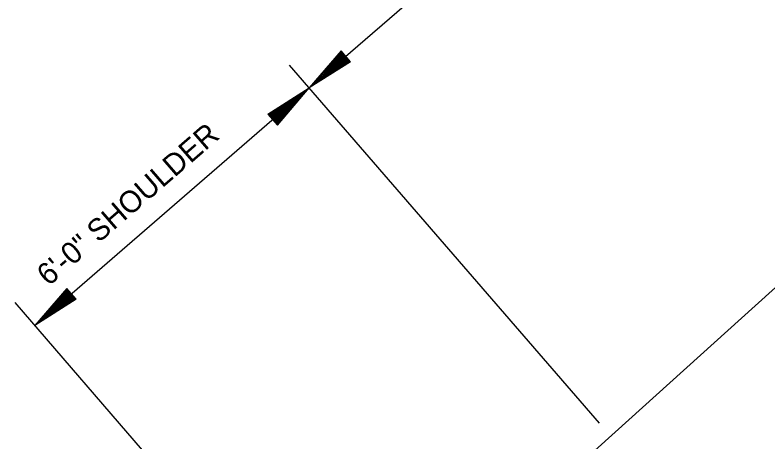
# Model space of a CAD drawing. Extents: x 192699 to 285914, y 194342 to 233219.
# Drawn here: x 262775.17 to 262787.62, y 213642.09 to 213649.15 of the extents above; entities that cross this region are included whole.
import ezdxf

# ---------------------------------------------------------------- set-up
doc = ezdxf.new("R2010")
doc.units = 0
doc.layers.add('TYPICAL SECTION FOR MOT', color=7, linetype='Continuous')

msp = doc.modelspace()

# ---------------------------------------------------------------- linework, layer by layer
at = {"layer": 'TYPICAL SECTION FOR MOT'}
for p, q in [((262804.337, 213659.599), (262780.377, 213638.004)), ((262780.038, 213647.943), (262791.379, 213657.761)), ((262780.565, 213648.558), (262780.038, 213647.943)), ((262780.578, 213648.542), (262780.139, 213648.031)), ((262780.722, 213648.376), (262780.565, 213648.558)), ((262780.591, 213648.527), (262780.244, 213648.121)), ((262780.604, 213648.512), (262780.344, 213648.208)), ((262780.682, 213648.422), (262780.344, 213648.208)), ((262780.618, 213648.497), (262780.447, 213648.297)), ((262780.669, 213648.438), (262780.447, 213648.297)), ((262780.631, 213648.481), (262780.548, 213648.384)), ((262780.656, 213648.453), (262780.548, 213648.384)), ((262784.837, 213642.4), (262779.711, 213648.321)), ((262780.722, 213648.376), (262780.038, 213647.943)), ((262780.709, 213648.391), (262780.139, 213648.031)), ((262780.695, 213648.407), (262780.244, 213648.121)), ((262775.502, 213644.016), (262780.038, 213647.943)), ((262779.355, 213647.51), (262780.038, 213647.943)), ((262779.512, 213647.329), (262780.038, 213647.943)), ((262779.368, 213647.495), (262779.937, 213647.856)), ((262779.499, 213647.344), (262779.937, 213647.856)), ((262779.382, 213647.48), (262779.833, 213647.766)), ((262779.395, 213647.465), (262779.733, 213647.679)), ((262779.473, 213647.375), (262779.733, 213647.679)), ((262779.486, 213647.359), (262779.833, 213647.766)), ((262779.408, 213647.449), (262779.63, 213647.59)), ((262779.459, 213647.39), (262779.63, 213647.59)), ((262779.355, 213647.51), (262779.512, 213647.329)), ((262779.421, 213647.434), (262779.529, 213647.502)), ((262779.446, 213647.405), (262779.529, 213647.502)), ((262776.029, 213644.63), (262775.502, 213644.016)), ((262776.042, 213644.615), (262775.603, 213644.104)), ((262776.055, 213644.6), (262775.707, 213644.194)), ((262776.068, 213644.585), (262775.808, 213644.281)), ((262776.081, 213644.569), (262775.91, 213644.37)), ((262776.186, 213644.449), (262776.029, 213644.63)), ((262776.186, 213644.449), (262775.502, 213644.016)), ((262776.173, 213644.464), (262775.603, 213644.104)), ((262776.159, 213644.48), (262775.707, 213644.194)), ((262776.146, 213644.495), (262775.808, 213644.281)), ((262776.132, 213644.51), (262775.91, 213644.37)), ((262776.095, 213644.554), (262776.011, 213644.457)), ((262776.119, 213644.526), (262776.011, 213644.457)), ((262780.301, 213638.473), (262775.175, 213644.394))]:
    msp.add_line(p, q, dxfattribs=at)

# ---------------------------------------------------------------- texts
msp.add_text('6\'-0" SHOULDER', height=0.36, rotation=40.8833, dxfattribs=at).set_placement((262775.731, 213644.656))

doc.saveas('drawing.dxf')
